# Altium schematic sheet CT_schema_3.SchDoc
size 282 x 169 mm
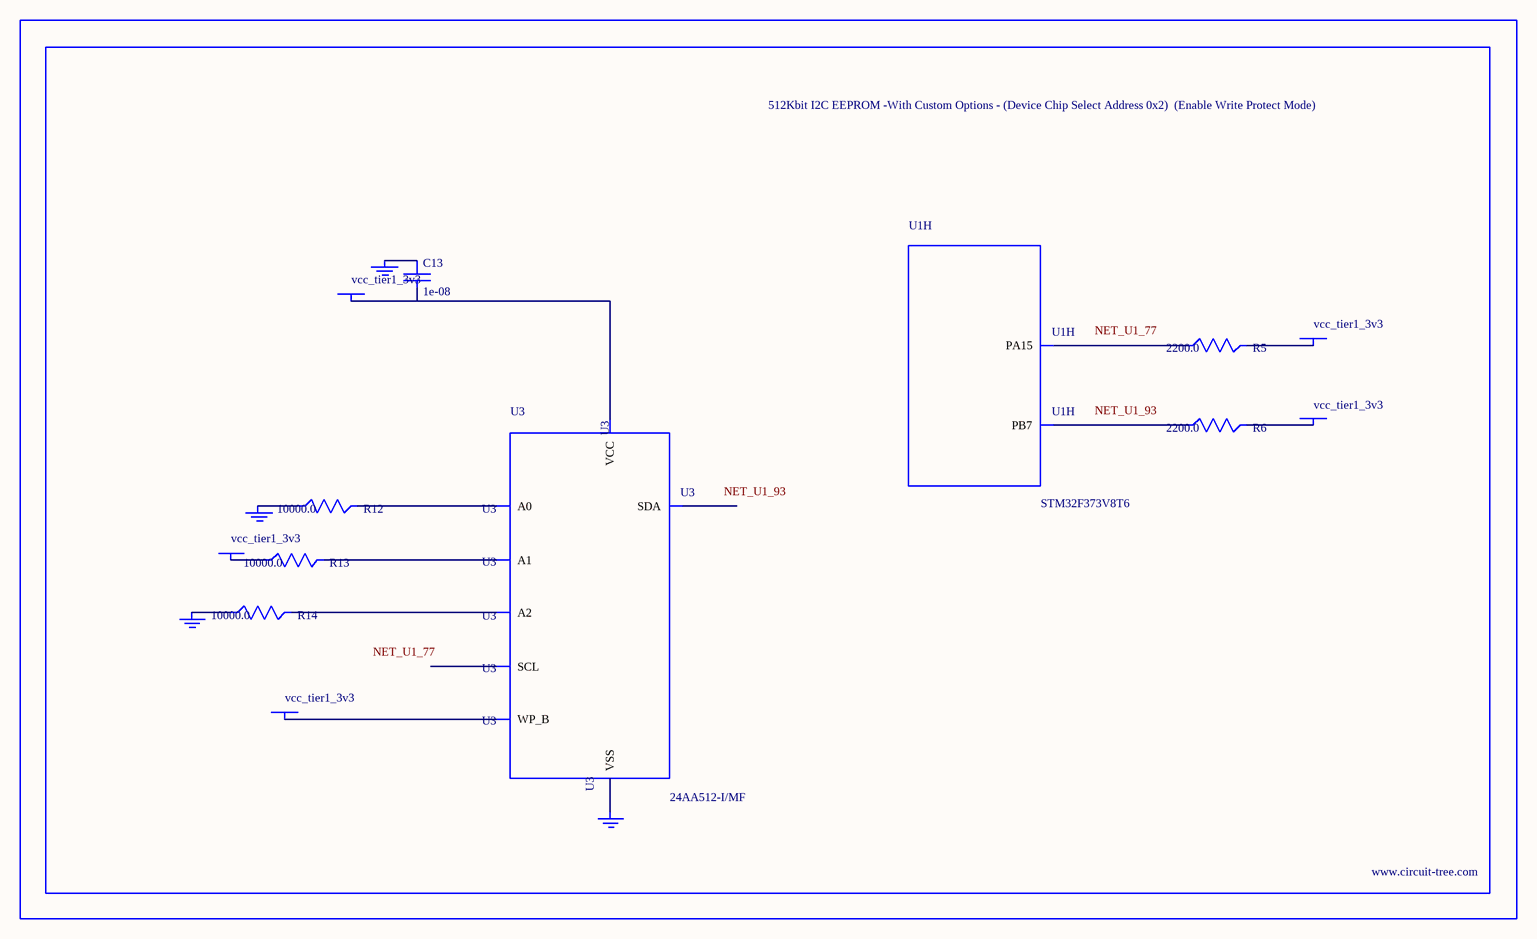
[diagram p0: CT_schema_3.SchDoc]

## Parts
BORDER2  (no value)
C13  1e-08  [C0402]
GND_INSTANCE_2_0  (no value)
GND_INSTANCE_2_1  (no value)
GND_INSTANCE_2_2  (no value)
GND_INSTANCE_2_3  (no value)
POWER_INSTANCE_2_0  vcc_tier1_3v3
POWER_INSTANCE_2_1  vcc_tier1_3v3
POWER_INSTANCE_2_2  vcc_tier1_3v3
POWER_INSTANCE_2_3  vcc_tier1_3v3
POWER_INSTANCE_2_4  vcc_tier1_3v3
R5  2200.0  [R0603]
R6  2200.0  [R0603]
R12  10000.0  [R0603]
R13  10000.0  [R0603]
R14  10000.0  [R0603]
U1  STM32F373V8T6  [LQFP100]  (part H of 10)
U3  24AA512-I/MF  [DFN8-S]

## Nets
NetC13_1: C13.1 GND_INSTANCE_2_2.0(GND)
NetC13_2: C13.2 POWER_INSTANCE_2_2.0(PWR) U3.8(VCC)
NetGND_INSTANCE_2_0_0: GND_INSTANCE_2_0.0(GND) R12.1
NetGND_INSTANCE_2_1_0: GND_INSTANCE_2_1.0(GND) R14.1
NetGND_INSTANCE_2_3_0: GND_INSTANCE_2_3.0(GND) U3.4(VSS)
NetPOWER_INSTANCE_2_0_0: POWER_INSTANCE_2_0.0(PWR) R13.1
NetPOWER_INSTANCE_2_1_0: POWER_INSTANCE_2_1.0(PWR) U3.7(WP_B)
NetPOWER_INSTANCE_2_3_0: POWER_INSTANCE_2_3.0(PWR) R5.2
NetPOWER_INSTANCE_2_4_0: POWER_INSTANCE_2_4.0(PWR) R6.2
NetR5_1: R5.1 U1.77(PA15)
NetR6_1: R6.1 U1.93(PB7)
NetR12_2: R12.2 U3.1(A0)
NetR13_2: R13.2 U3.2(A1)
NetR14_2: R14.2 U3.3(A2)

Not connected (* = marked no-connect by the designer): U3 5(SDA) 6(SCL)

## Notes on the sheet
- Labels drawn without touching a wire or pin: NET_U1_77, NET_U1_93

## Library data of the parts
BORDER2 = BORDER_PAGE2
C13 = C0402C103K3RAC
GND_INSTANCE_2_0-GND_INSTANCE_2_3 = GND
POWER_INSTANCE_2_0-POWER_INSTANCE_2_4 = PWR
R5 R6 = RC0603JR-072K2L
R12-R14 = RC0603JR-0710KL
